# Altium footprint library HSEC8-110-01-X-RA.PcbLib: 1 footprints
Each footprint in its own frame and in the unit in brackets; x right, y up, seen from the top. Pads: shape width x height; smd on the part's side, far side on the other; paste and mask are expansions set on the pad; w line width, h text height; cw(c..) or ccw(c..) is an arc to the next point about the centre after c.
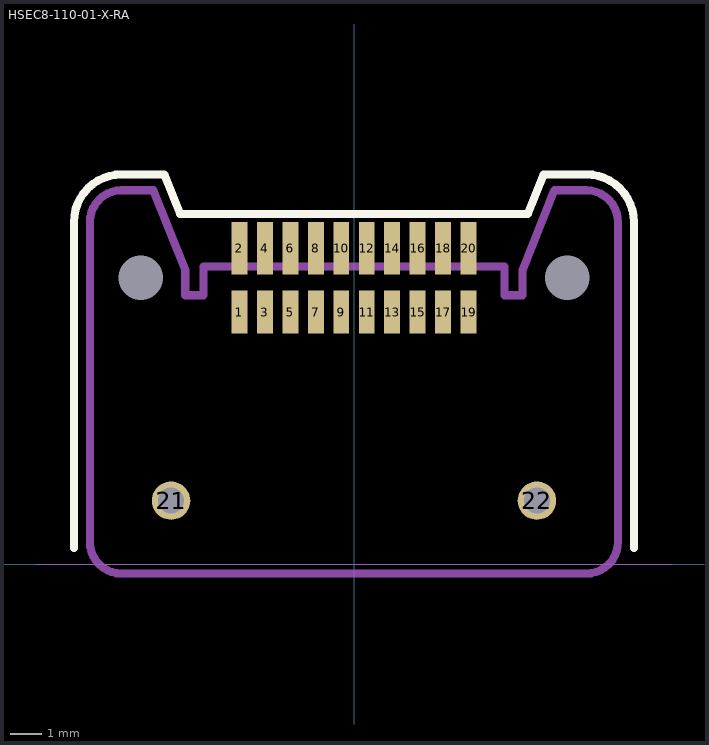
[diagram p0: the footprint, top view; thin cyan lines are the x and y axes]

## HSEC8-110-01-X-RA [mm]
pads (24):
  rect 0.5x1.35 smd mask+0.05: 1(-3.6,7.925) 3(-2.8,7.925) 5(-2,7.925) 7(-1.2,7.925) 9(-0.4,7.925) 11(0.4,7.925) 13(1.2,7.925) 15(2,7.925) 17(2.8,7.925) 19(3.6,7.925)
  rect 0.5x1.65 smd mask+0.05: 2(-3.6,9.925) 4(-2.8,9.925) 6(-2,9.925) 8(-1.2,9.925) 10(-0.4,9.925) 12(0.4,9.925) 14(1.2,9.925) 16(2,9.925) 18(2.8,9.925) 20(3.6,9.925)
  round 1.21 hole 0.81 mask+0.075: 21(-5.75,2) 22(5.75,2)
  round 0 hole 1.4 unplated: 23(-6.7,9) 24(6.7,9)
Top Overlay:
  lines w0.254: -8.803,0.504 -8.803,10.754 cw(c-7.303,10.754) -7.303,12.254 -5.964,12.254 -5.466,11.008 5.46,11.008 5.959,12.254 7.297,12.254 cw(c7.297,10.754) 8.797,10.754 8.797,0.504
Mechanical 1:
  lines w0.254: -8.303,0.704 ccw(c-7.303,0.704) -7.303,-0.296 -5.988,-0.296 -5.518,-0.296 5.512,-0.296 5.982,-0.296 6.097,-0.296 6.497,-0.296 6.897,-0.296 7.297,-0.296 ccw(c7.297,0.704) 8.297,0.704 8.297,10.754 ccw(c7.297,10.754) 7.297,11.754 6.297,11.754 5.297,9.254 5.297,8.454 4.727,8.454 4.727,9.354 -4.733,9.354 -4.733,8.454 -5.303,8.454 -5.303,9.254 -6.303,11.754 -7.303,11.754 ccw(c-7.303,10.754) -8.303,10.754 -8.303,0.704
  text "J1" at -0.446,4.369 h0.76
Mechanical 16:
  lines w0.01: -10,0 10,0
